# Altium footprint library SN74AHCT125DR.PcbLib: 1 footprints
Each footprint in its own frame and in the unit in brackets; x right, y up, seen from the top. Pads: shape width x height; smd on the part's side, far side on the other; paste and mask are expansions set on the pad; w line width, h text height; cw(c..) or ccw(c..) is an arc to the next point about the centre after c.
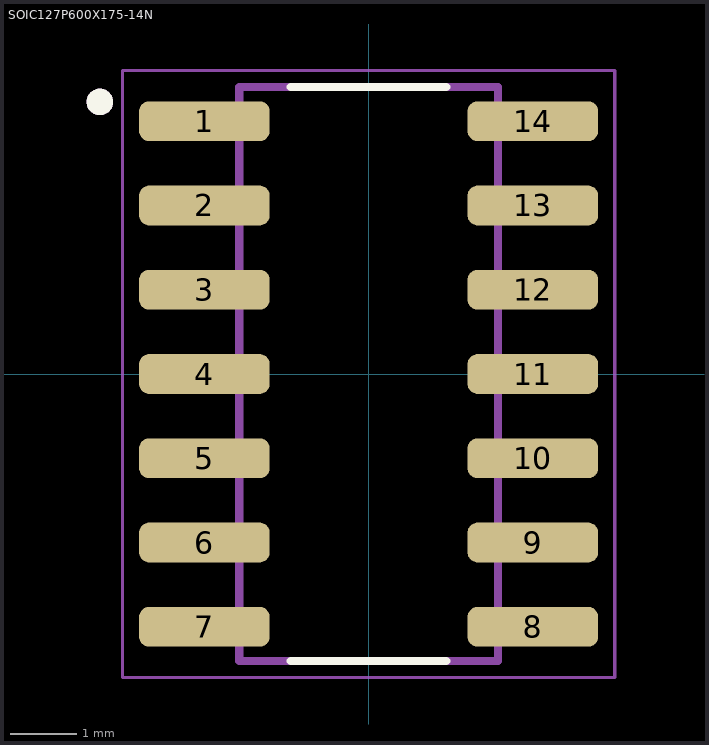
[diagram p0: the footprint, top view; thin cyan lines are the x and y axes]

## SOIC127P600X175-14N [mm]
pads (14):
  rrect50% 1.97x0.6 smd paste+0 mask+0.102: 1(-2.475,3.81) 2(-2.475,2.54) 3(-2.475,1.27) 4(-2.475,0) 5(-2.475,-1.27) 6(-2.475,-2.54) 7(-2.475,-3.81) 8(2.475,-3.81) 9(2.475,-2.54) 10(2.475,-1.27) 11(2.475,0) 12(2.475,1.27) 13(2.475,2.54) 14(2.475,3.81)
Top Overlay:
  circle w0.2: c-4.05,4.1 r0.1
  lines w0.127: -1.17,-4.325 1.17,-4.325 ; -1.17,4.325 1.17,4.325
Assembly Top:
  circle w0.2: c-4.05,4.1 r0.1
  lines w0.127: -1.95,-4.325 1.95,-4.325 1.95,4.325 -1.95,4.325 -1.95,-4.325
Courtyard Top:
  lines w0.05: -3.71,-4.575 3.71,-4.575 3.71,4.575 -3.71,4.575 -3.71,-4.575
3D body "step_temp.STEP": height 1.75, standoff 0, extent -3,-4.325 3,4.325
